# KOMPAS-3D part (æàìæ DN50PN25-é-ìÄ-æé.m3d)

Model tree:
1. Объединить компоненты:1  (labels: СЕНС DN50PN25-В-НО)
2. Эскиз:1
3. Операция выдавливания:1
     Расстояние 1 = 14
4. Фаска:1
     Угол = 45; Длина 1 = 2; Длина 2 = 2

Referenced files in D:\Савин\!СЕНСОР\3D для заказчика\!Новый перечень\СЕНС\6. СЕНС-В-НО\DN50\: СЕНС DN50PN25-В-НО.a3d
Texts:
  СЕНС DN50PN25-В-НО-СВ
  ООО НПП Сенсор
  СЕНС DN50PN25-В-НО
